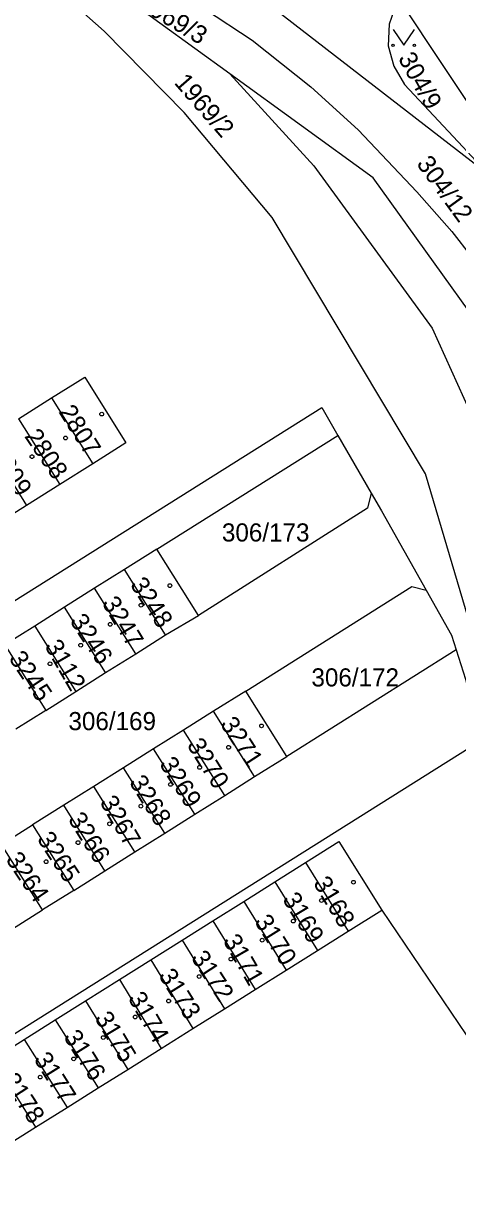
# Model space of a CAD drawing. Extents: x -679220 to -673243, y -1075091 to -1066557.
# Drawn here: x -676104.3 to -676063.6, y -1072493.4 to -1072382.5 of the extents above; entities that cross this region are included whole.
import ezdxf

# ---------------------------------------------------------------- set-up
doc = ezdxf.new("R2010")
doc.units = 0
for name, color, linetype in [('Hranice parcel', 7, 'Continuous'), ('Parcelní čísla', 7, 'Continuous'), ('Značky budov', 7, 'Continuous'), ('Značky kultur', 7, 'Continuous')]:
    doc.layers.add(name, color=color, linetype=linetype)

msp = doc.modelspace()

# ---------------------------------------------------------------- linework, layer by layer
at = {"layer": 'Hranice parcel'}
for p, q in [((-676084.95, -1072387.22), (-676117.22, -1072363.74)), ((-676104.78, -1072419.6), (-676101.68, -1072417.64)), ((-676101.68, -1072417.64), (-676097.82, -1072423.81)), ((-676104.78, -1072419.6), (-676100.92, -1072425.77)), ((-676091.82, -1072431.84), (-676074.81, -1072421.15)), ((-676074.81, -1072421.15), (-676071.68, -1072426.57)), ((-676107.89, -1072421.55), (-676104.03, -1072427.72)), ((-676097.82, -1072423.81), (-676100.92, -1072425.77)), ((-676100.92, -1072425.77), (-676104.03, -1072427.72)), ((-676104.03, -1072427.72), (-676107.13, -1072429.67)), ((-676091.82, -1072431.84), (-676094.84, -1072433.74)), ((-676087.9, -1072438.04), (-676091.82, -1072431.84)), ((-676094.84, -1072433.74), (-676097.65, -1072435.5)), ((-676090.98, -1072439.88), (-676094.84, -1072433.74)), ((-676097.65, -1072435.5), (-676100.46, -1072437.27)), ((-676093.79, -1072441.65), (-676097.65, -1072435.5)), ((-676100.46, -1072437.27), (-676103.27, -1072439.04)), ((-676096.61, -1072443.41), (-676100.46, -1072437.27)), ((-676090.98, -1072439.88), (-676087.9, -1072438.04)), ((-676103.27, -1072439.04), (-676106.08, -1072440.8)), ((-676103.27, -1072439.04), (-676099.42, -1072445.18)), ((-676093.79, -1072441.65), (-676090.98, -1072439.88)), ((-676106.08, -1072440.8), (-676102.23, -1072446.95)), ((-676096.61, -1072443.41), (-676093.79, -1072441.65)), ((-676063.71, -1072441.28), (-676079.61, -1072451.28)), ((-676099.42, -1072445.18), (-676096.61, -1072443.41)), ((-676102.23, -1072446.95), (-676099.42, -1072445.18)), ((-676083.47, -1072445.14), (-676086.48, -1072447.03)), ((-676079.61, -1072451.28), (-676083.47, -1072445.14)), ((-676102.23, -1072446.95), (-676105.04, -1072448.71)), ((-676086.48, -1072447.03), (-676089.29, -1072448.8)), ((-676082.63, -1072453.17), (-676086.48, -1072447.03)), ((-676089.29, -1072448.8), (-676092.11, -1072450.57)), ((-676085.44, -1072454.94), (-676089.29, -1072448.8)), ((-676092.11, -1072450.57), (-676094.92, -1072452.33)), ((-676088.25, -1072456.7), (-676092.11, -1072450.57)), ((-676082.63, -1072453.17), (-676079.61, -1072451.28)), ((-676094.92, -1072452.33), (-676097.73, -1072454.1)), ((-676091.06, -1072458.47), (-676094.92, -1072452.33)), ((-676085.44, -1072454.94), (-676082.63, -1072453.17)), ((-676097.73, -1072454.1), (-676100.54, -1072455.86)), ((-676093.87, -1072460.24), (-676097.73, -1072454.1)), ((-676088.25, -1072456.7), (-676085.44, -1072454.94)), ((-676100.54, -1072455.86), (-676103.46, -1072457.7)), ((-676096.68, -1072462), (-676100.54, -1072455.86)), ((-676091.06, -1072458.47), (-676088.25, -1072456.7)), ((-676106.38, -1072459.54), (-676103.46, -1072457.7)), ((-676103.46, -1072457.7), (-676099.6, -1072463.84)), ((-676093.87, -1072460.24), (-676091.06, -1072458.47)), ((-676102.52, -1072465.68), (-676106.38, -1072459.54)), ((-676096.68, -1072462), (-676093.87, -1072460.24)), ((-676099.6, -1072463.84), (-676096.68, -1072462)), ((-676080.72, -1072463.04), (-676077.85, -1072461.24)), ((-676077.85, -1072461.24), (-676073.86, -1072467.68)), ((-676083.65, -1072464.88), (-676080.72, -1072463.04)), ((-676080.72, -1072463.04), (-676076.73, -1072469.48)), ((-676099.6, -1072463.84), (-676102.52, -1072465.68)), ((-676086.55, -1072466.7), (-676083.65, -1072464.88)), ((-676083.65, -1072464.88), (-676079.67, -1072471.32)), ((-676105.34, -1072467.44), (-676102.52, -1072465.68)), ((-676089.44, -1072468.52), (-676086.55, -1072466.7)), ((-676086.55, -1072466.7), (-676082.57, -1072473.14)), ((-676073.86, -1072467.68), (-676070.69, -1072465.69)), ((-676076.73, -1072469.48), (-676073.86, -1072467.68)), ((-676092.38, -1072470.36), (-676089.44, -1072468.52)), ((-676089.44, -1072468.52), (-676085.46, -1072474.95)), ((-676079.67, -1072471.32), (-676076.73, -1072469.48)), ((-676095.32, -1072472.21), (-676092.38, -1072470.36)), ((-676092.38, -1072470.36), (-676088.43, -1072476.81)), ((-676098.51, -1072474.21), (-676095.32, -1072472.21)), ((-676095.32, -1072472.21), (-676091.4, -1072478.67)), ((-676082.57, -1072473.14), (-676079.67, -1072471.32)), ((-676085.46, -1072474.95), (-676082.57, -1072473.14)), ((-676101.34, -1072475.99), (-676098.51, -1072474.21)), ((-676098.51, -1072474.21), (-676094.54, -1072480.64)), ((-676088.43, -1072476.81), (-676085.46, -1072474.95)), ((-676104.25, -1072477.82), (-676101.34, -1072475.99)), ((-676101.34, -1072475.99), (-676097.3, -1072482.37)), ((-676091.4, -1072478.67), (-676088.43, -1072476.81)), ((-676107.19, -1072479.66), (-676104.25, -1072477.82)), ((-676104.25, -1072477.82), (-676100.22, -1072484.2)), ((-676094.54, -1072480.64), (-676091.4, -1072478.67)), ((-676107.19, -1072479.66), (-676103.19, -1072486.07)), ((-676097.3, -1072482.37), (-676094.54, -1072480.64)), ((-676100.22, -1072484.2), (-676097.3, -1072482.37)), ((-676103.19, -1072486.07), (-676100.22, -1072484.2)), ((-676106.08, -1072487.88), (-676103.19, -1072486.07))]:
    msp.add_line(p, q, dxfattribs=at)
for points in [[(-676060.65, -1072396.71), (-676088.94, -1072374.82), (-676097.4, -1072369.15), (-676135.11, -1072342.81)], [(-676117.22, -1072363.74), (-676116.34, -1072363.6), (-676089.85, -1072379.52), (-676087.32, -1072381.13), (-676082.85, -1072384.09), (-676077.34, -1072388.44), (-676072.91, -1072392.49), (-676067.41, -1072398.29), (-676064.13, -1072402.03), (-676062.28, -1072404.41), (-676059.34, -1072408.48), (-676056.62, -1072412.67), (-676054.33, -1072416.58), (-676055.95, -1072418.63)], [(-676064.43, -1072530.6), (-676060.93, -1072514.33), (-676058.84, -1072500.85), (-676057.79, -1072483.42), (-676057.73, -1072462.91), (-676058.94, -1072451.8), (-676060.84, -1072444.17), (-676066.6, -1072424.75), (-676080.98, -1072400.72), (-676089.25, -1072390.86), (-676096.74, -1072383.24), (-676106.51, -1072374.56), (-676118.43, -1072364.57)], [(-676069.02, -1072380.25), (-676069.35, -1072380.69), (-676070, -1072382.58), (-676070.09, -1072384.61), (-676069.58, -1072386.51), (-676068.57, -1072388.23), (-676063.1, -1072394.07), (-676060.65, -1072396.71)], [(-676047.06, -1072413.1), (-676056.32, -1072399.44), (-676069.02, -1072380.25)], [(-676055.95, -1072418.63), (-676071.52, -1072396.99), (-676084.95, -1072387.22)], [(-676084.95, -1072387.22), (-676077.08, -1072395.86), (-676065.96, -1072411.11), (-676061.23, -1072421.61), (-676052.78, -1072452.85), (-676052.01, -1072462.63), (-676051.68, -1072475.56), (-676052.77, -1072491.68), (-676054.32, -1072506.68), (-676056.64, -1072523.56), (-676061.06, -1072535.34)], [(-676101.68, -1072417.64), (-676098.57, -1072415.69), (-676094.71, -1072421.86), (-676097.82, -1072423.81)], [(-676156.45, -1072486.01), (-676164.15, -1072473.75), (-676076.31, -1072418.55), (-676074.81, -1072421.15)], [(-676071.68, -1072426.57), (-676072.03, -1072427.97), (-676087.9, -1072438.04)], [(-676071.68, -1072426.57), (-676070.73, -1072428.23), (-676066.53, -1072435.67)], [(-676083.47, -1072445.14), (-676067.87, -1072435.33), (-676066.53, -1072435.67)], [(-676066.53, -1072435.67), (-676064.15, -1072439.9), (-676063.71, -1072441.28)], [(-676063.71, -1072441.28), (-676062.84, -1072444.02), (-676061.41, -1072449.82), (-676145.85, -1072502.88), (-676156.45, -1072486.01)], [(-676077.85, -1072461.24), (-676074.72, -1072459.27), (-676070.69, -1072465.69)], [(-676070.69, -1072465.69), (-676059.17, -1072482.71), (-676060.35, -1072503.43), (-676065.77, -1072528.95), (-676076.34, -1072567.38), (-676083.41, -1072584.95), (-676093.32, -1072601.73), (-676100.75, -1072617.65), (-676109.37, -1072640.15)]]:
    msp.add_lwpolyline(points, dxfattribs=at)
at = {"layer": 'Značky budov'}
for centre in [(-676096.98, -1072419.16), (-676100.37, -1072421.4), (-676103.52, -1072423.15), (-676090.58, -1072435.25), (-676093.29, -1072437.09), (-676096.18, -1072438.88), (-676098.95, -1072440.84), (-676101.83, -1072442.58), (-676081.98, -1072448.41), (-676085.07, -1072450.42), (-676087.79, -1072452.3), (-676090.53, -1072453.9), (-676093.3, -1072455.94), (-676096.24, -1072457.6), (-676099.2, -1072459.36), (-676102.2, -1072461.15), (-676073.36, -1072463.08), (-676076.36, -1072464.79), (-676079, -1072466.72), (-676081.92, -1072468.51), (-676084.85, -1072470.29), (-676087.84, -1072471.93), (-676090.7, -1072474.22), (-676093.83, -1072475.72), (-676096.83, -1072477.65), (-676099.61, -1072479.65), (-676102.75, -1072481.36)]:
    msp.add_circle(centre, 0.175, dxfattribs=at)
at = {"layer": 'Značky kultur'}
msp.add_lwpolyline([(-676069.64, -1072383.06), (-676068.64, -1072384.56), (-676067.64, -1072383.06)], dxfattribs=at)
for centre in [(-676069.64, -1072384.56), (-676067.64, -1072384.56)]:
    msp.add_circle(centre, 0.1, dxfattribs=at)

# ---------------------------------------------------------------- texts
at = {"layer": 'Parcelní čísla'}
for s, rotation, p in [('1969/3', 329, (-676093.7, -1072380.97)), ('304/9', 299, (-676069.21, -1072385.77)), ('1969/2', 311, (-676090.25, -1072388.1)), ('304/12', 306, (-676067.5, -1072395.68)), ('2807', 302, (-676101.07, -1072418.94)), ('2808', 304, (-676104.28, -1072421.24)), ('2809', 302, (-676107.54, -1072422.73)), ('3248', 303, (-676094.37, -1072435.14)), ('3247', 301, (-676097.01, -1072436.88)), ('3246', 303, (-676100.02, -1072438.57)), ('3112', 300, (-676102.38, -1072440.91)), ('3245', 304, (-676105.75, -1072442.08)), ('3271', 303, (-676085.91, -1072448.23)), ('3270', 302, (-676089.03, -1072450.2)), ('3269', 302, (-676091.62, -1072451.97)), ('3268', 302, (-676094.46, -1072453.68)), ('3267', 300, (-676097.21, -1072455.54)), ('3266', 302, (-676100.19, -1072457.16)), ('3265', 303, (-676103.1, -1072459.01)), ('3264', 304, (-676106.04, -1072460.94)), ('3168', 301, (-676077.18, -1072463.15)), ('3169', 301, (-676080.07, -1072464.65)), ('3170', 302, (-676082.7, -1072466.76)), ('3171', 300, (-676085.65, -1072468.55)), ('3172', 303, (-676088.65, -1072470.16)), ('3173', 302, (-676091.69, -1072471.83)), ('3174', 300, (-676094.56, -1072473.95)), ('3175', 301, (-676097.69, -1072475.82)), ('3176', 302, (-676100.61, -1072477.58)), ('3177', 302, (-676103.4, -1072479.67)), ('3178', 303, (-676106.39, -1072481.64))]:
    msp.add_text(s, height=1.7, rotation=rotation, dxfattribs=at).set_placement(p)
for s, p in [('306/173', (-676085.7, -1072431.11)), ('306/172', (-676077.3, -1072444.71)), ('306/169', (-676100.1, -1072448.81))]:
    msp.add_text(s, height=1.7, dxfattribs=at).set_placement(p)

doc.saveas('drawing.dxf')
